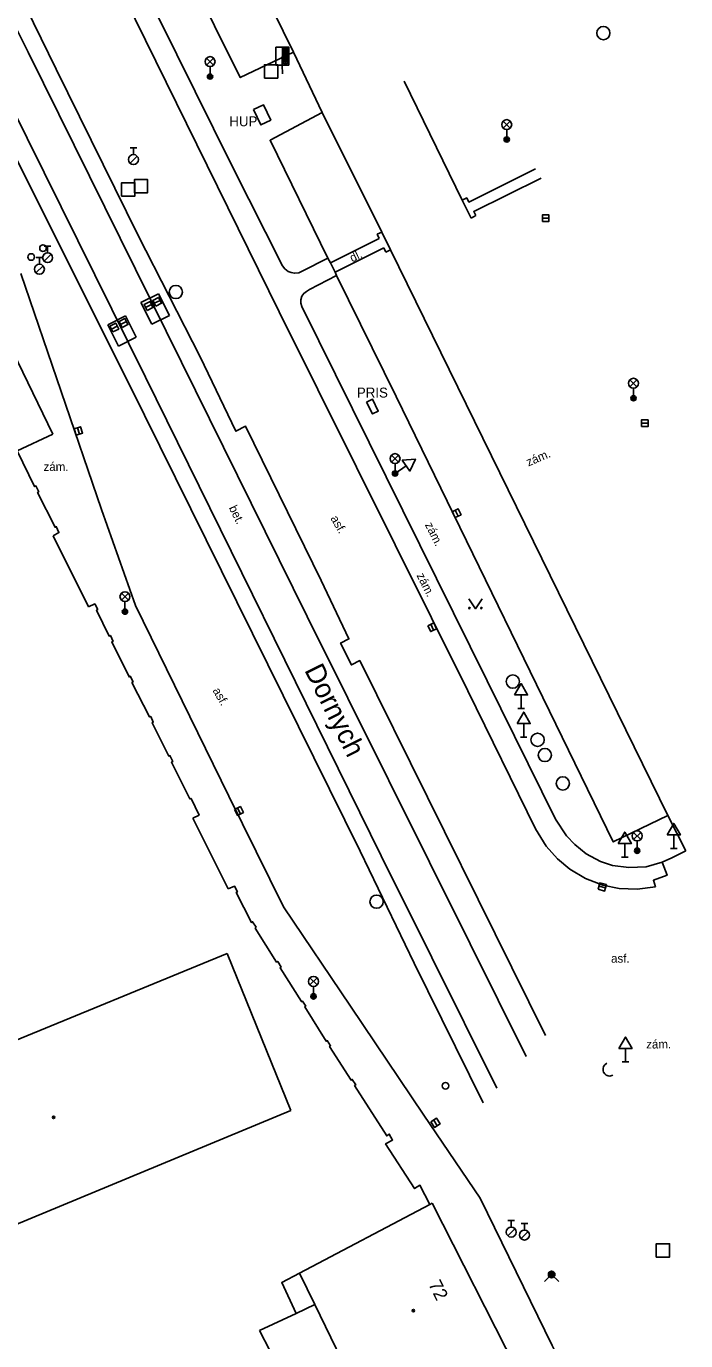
# Model space of a CAD drawing. Extents: x -598341 to -594502, y -1162301 to -1161406.
# Drawn here: x -597409.8 to -597360.1, y -1161848 to -1161748.9 of the extents above; entities that cross this region are included whole.
import ezdxf

# ---------------------------------------------------------------- set-up
doc = ezdxf.new("R2010")
doc.units = 0
for name, color, linetype in [('Vrstva 10', 7, 'Continuous'), ('Vrstva 11', 7, 'Continuous'), ('Vrstva 13', 7, 'Continuous'), ('Vrstva 24', 7, 'Continuous'), ('Vrstva 25', 7, 'Continuous'), ('Vrstva 26', 7, 'Continuous'), ('Vrstva 27', 7, 'Continuous'), ('Vrstva 28', 7, 'Continuous'), ('Vrstva 31', 7, 'Continuous'), ('Vrstva 33', 7, 'Continuous'), ('Vrstva 34', 7, 'Continuous'), ('Vrstva 36', 7, 'Continuous'), ('Vrstva 39', 7, 'Continuous'), ('Vrstva 40', 7, 'Continuous'), ('Vrstva 41', 7, 'Continuous'), ('Vrstva 46', 7, 'Continuous'), ('Vrstva 49', 7, 'Continuous'), ('Vrstva 5', 7, 'Continuous'), ('Vrstva 7', 7, 'Continuous'), ('Vrstva 8', 7, 'Continuous')]:
    doc.layers.add(name, color=color, linetype=linetype)

msp = doc.modelspace()

# ---------------------------------------------------------------- linework, layer by layer
at = {"layer": 'Vrstva 10'}
for p, q in [((-597386.89, -1161766.75), (-597387.07, -1161766.41)), ((-597386.53, -1161767.46), (-597386.89, -1161766.75)), ((-597386.42, -1161767.72), (-597386.53, -1161767.46))]:
    msp.add_line(p, q, dxfattribs=at)
for points in [[(-597389.67, -1161750.87), (-597393.69, -1161752.79), (-597397.56, -1161744.97), (-597401.57, -1161737.23), (-597397.36, -1161735.2)], [(-597371.42, -1161809.44), (-597376.52, -1161799.05), (-597381.99, -1161788.02), (-597390.76, -1161770.46), (-597405.49, -1161740.5), (-597407.78, -1161736.02)], [(-597387.5, -1161755.43), (-597389.67, -1161750.87)], [(-597387.07, -1161766.41), (-597391.44, -1161757.51), (-597387.5, -1161755.43)], [(-597410.23, -1161767.56), (-597404.14, -1161785.35), (-597401.58, -1161792.6), (-597394.55, -1161806.99), (-597390.42, -1161815.33), (-597385.37, -1161822.82), (-597379.83, -1161831.05), (-597375.6, -1161837.3), (-597370.15, -1161848.42), (-597368.22, -1161852.29)], [(-597361.45, -1161808.45), (-597365.56, -1161810.43), (-597381.92, -1161776.84), (-597386.42, -1161767.72)], [(-597360.09, -1161811.11), (-597361.45, -1161808.45)], [(-597371.42, -1161809.44), (-597370.61, -1161810.76), (-597369.75, -1161811.72), (-597368.83, -1161812.49), (-597367.64, -1161813.18), (-597366.34, -1161813.69), (-597365.11, -1161813.94), (-597363.76, -1161813.99), (-597362.36, -1161813.81)], [(-597365.59, -1161828.03), (-597365.81, -1161828.09), (-597365.94, -1161828.07), (-597366.08, -1161828.02), (-597366.2, -1161827.92), (-597366.28, -1161827.8), (-597366.32, -1161827.69), (-597366.32, -1161827.53), (-597366.29, -1161827.38), (-597366.19, -1161827.25), (-597366.04, -1161827.12)]]:
    msp.add_lwpolyline(points, dxfattribs=at)
at = {"layer": 'Vrstva 11'}
for p, q in [((-597381.32, -1161753.06), (-597376.96, -1161762.04)), ((-597383, -1161764.44), (-597387.5, -1161755.43)), ((-597383.2, -1161764.93), (-597386.89, -1161766.75)), ((-597383, -1161764.44), (-597383.36, -1161764.61)), ((-597383.36, -1161764.61), (-597383.2, -1161764.93)), ((-597383, -1161764.44), (-597382.35, -1161765.79)), ((-597386.53, -1161767.46), (-597382.85, -1161765.64)), ((-597382.85, -1161765.64), (-597382.7, -1161765.95)), ((-597382.7, -1161765.95), (-597382.35, -1161765.79)), ((-597361.45, -1161808.45), (-597382.35, -1161765.79)), ((-597387.07, -1161766.41), (-597389.01, -1161767.39)), ((-597388.45, -1161768.77), (-597386.42, -1161767.72)), ((-597401.17, -1161769.76), (-597399.84, -1161769.09)), ((-597400.36, -1161771.39), (-597401.17, -1161769.76)), ((-597399.84, -1161769.09), (-597399.03, -1161770.73)), ((-597403.67, -1161771.43), (-597402.34, -1161770.75)), ((-597402.34, -1161770.75), (-597401.53, -1161772.37)), ((-597399.03, -1161770.73), (-597400.36, -1161771.39)), ((-597402.87, -1161773.04), (-597403.67, -1161771.43)), ((-597401.53, -1161772.37), (-597402.87, -1161773.04))]:
    msp.add_line(p, q, dxfattribs=at)
for points in [[(-597375.36, -1161830.11), (-597380.56, -1161819.58), (-597384.65, -1161811.14), (-597402.07, -1161775.92), (-597412.64, -1161754.81), (-597417.86, -1161744.11), (-597420.13, -1161739.67), (-597423.19, -1161733.58), (-597428.01, -1161724.62)], [(-597370.66, -1161825.04), (-597374.47, -1161817.36), (-597384.67, -1161796.76), (-597385.3, -1161797.08), (-597386.12, -1161795.44), (-597385.49, -1161795.12), (-597387.58, -1161790.72), (-597393.28, -1161779.09), (-597394.01, -1161779.46), (-597396.71, -1161773.85), (-597401.38, -1161764.71), (-597407.57, -1161752.16), (-597411.57, -1161743.95), (-597417.12, -1161732.94), (-597417.69, -1161733.22)], [(-597390.5, -1161766.98), (-597394.33, -1161759.43), (-597404.02, -1161739.8), (-597407.38, -1161733.04), (-597398.74, -1161732.44)], [(-597389.67, -1161750.87), (-597397.36, -1161735.2)], [(-597371.42, -1161759.67), (-597376.44, -1161762.18), (-597376.6, -1161761.86), (-597376.96, -1161762.04)], [(-597375.92, -1161763.2), (-597376.08, -1161762.89), (-597370.98, -1161760.38)], [(-597376.96, -1161762.04), (-597376.28, -1161763.38)], [(-597376.28, -1161763.38), (-597375.92, -1161763.2)], [(-597390.5, -1161766.98), (-597390.32, -1161767.22), (-597390.08, -1161767.41), (-597389.84, -1161767.5), (-597389.6, -1161767.55), (-597389.27, -1161767.51), (-597389.01, -1161767.39)], [(-597389.05, -1161770.06), (-597389.11, -1161769.81), (-597389.12, -1161769.56), (-597389.03, -1161769.28), (-597388.89, -1161769.07), (-597388.7, -1161768.91), (-597388.45, -1161768.77)], [(-597369.9, -1161808.72), (-597375.07, -1161798.28), (-597389.05, -1161770.06)], [(-597361.87, -1161811.97), (-597363.08, -1161812.31), (-597364.37, -1161812.36), (-597365.61, -1161812.22), (-597366.51, -1161811.9), (-597367.59, -1161811.33), (-597368.46, -1161810.63), (-597369.09, -1161809.97), (-597369.9, -1161808.72)], [(-597361.14, -1161811.64), (-597360.09, -1161811.11)], [(-597361.87, -1161811.97), (-597361.49, -1161812.95), (-597362.52, -1161813.32), (-597362.36, -1161813.81)], [(-597361.87, -1161811.97), (-597361.14, -1161811.64)], [(-597389.47, -1161846), (-597390.55, -1161843.65), (-597389.21, -1161842.95)]]:
    msp.add_lwpolyline(points, dxfattribs=at)
at = {"layer": 'Vrstva 13'}
for points in [[(-597372.12, -1161826.62), (-597376.34, -1161818.13), (-597388.64, -1161793.42), (-597398.12, -1161774.25), (-597409.67, -1161750.87), (-597418.39, -1161733.44), (-597422.33, -1161726)], [(-597425.21, -1161726.89), (-597421.25, -1161734.37), (-597415.51, -1161745.76), (-597412.33, -1161752.23), (-597400.82, -1161775.37), (-597383.06, -1161811.47), (-597379.23, -1161819.14), (-597374.33, -1161829)]]:
    msp.add_lwpolyline(points, dxfattribs=at)
at = {"layer": 'Vrstva 24'}
msp.add_lwpolyline([(-597392.69, -1161755.2), (-597391.94, -1161754.84), (-597391.38, -1161756), (-597392.14, -1161756.36), (-597392.69, -1161755.2)], dxfattribs=at)
msp.add_lwpolyline([(-597384.166, -1161777.262), (-597383.723, -1161778.159), (-597383.275, -1161777.937), (-597383.718, -1161777.041)], close=True, dxfattribs=at)
at = {"layer": 'Vrstva 25'}
for p, q in [((-597391.012, -1161751.848), (-597391.012, -1161750.501)), ((-597391.012, -1161750.501), (-597390.511, -1161750.501)), ((-597390.511, -1161751.848), (-597391.012, -1161751.848)), ((-597390.51, -1161752.5), (-597390.511, -1161751.849))]:
    msp.add_line(p, q, dxfattribs=at)
for points in [[(-597390.01, -1161751.849), (-597390.511, -1161751.849), (-597390.51, -1161750.5), (-597390.011, -1161750.5)], [(-597390.11, -1161751.748), (-597390.41, -1161751.749), (-597390.409, -1161750.6), (-597390.111, -1161750.6)], [(-597390.21, -1161751.649), (-597390.31, -1161751.649), (-597390.31, -1161750.7), (-597390.21, -1161750.7)]]:
    msp.add_lwpolyline(points, close=True, dxfattribs=at)
at = {"layer": 'Vrstva 26'}
for points in [[(-597391.86, -1161752.82), (-597390.86, -1161752.82), (-597390.86, -1161751.82), (-597391.86, -1161751.82)], [(-597402.63, -1161761.72), (-597401.63, -1161761.72), (-597401.63, -1161760.72), (-597402.63, -1161760.72)], [(-597401.67, -1161761.48), (-597400.67, -1161761.48), (-597400.67, -1161760.48), (-597401.67, -1161760.48)], [(-597362.31, -1161841.74), (-597361.31, -1161841.74), (-597361.31, -1161840.74), (-597362.31, -1161840.74)]]:
    msp.add_lwpolyline(points, close=True, dxfattribs=at)
at = {"layer": 'Vrstva 27'}
for p, q in [((-597370.9, -1161763.39), (-597370.4, -1161763.39)), ((-597400.174, -1161769.812), (-597399.727, -1161769.588)), ((-597400.824, -1161770.132), (-597400.377, -1161769.908)), ((-597403.404, -1161771.752), (-597402.957, -1161771.528)), ((-597402.714, -1161771.412), (-597402.267, -1161771.188)), ((-597405.97, -1161779.203), (-597405.811, -1161779.677)), ((-597363.43, -1161778.86), (-597362.93, -1161778.86)), ((-597377.481, -1161785.416), (-597377.259, -1161785.864)), ((-597379.321, -1161794.016), (-597379.099, -1161794.464)), ((-597393.891, -1161807.876), (-597393.669, -1161808.324)), ((-597366.621, -1161813.764), (-597366.139, -1161813.896)), ((-597379.092, -1161831.407), (-597378.828, -1161831.832))]:
    msp.add_line(p, q, dxfattribs=at)
for points in [[(-597370.9, -1161763.64), (-597370.4, -1161763.64), (-597370.4, -1161763.14), (-597370.9, -1161763.14)], [(-597400.712, -1161770.355), (-597400.265, -1161770.132), (-597400.488, -1161769.685), (-597400.936, -1161769.908)], [(-597400.062, -1161770.035), (-597399.615, -1161769.812), (-597399.838, -1161769.365), (-597400.286, -1161769.588)], [(-597403.292, -1161771.975), (-597402.845, -1161771.752), (-597403.068, -1161771.305), (-597403.516, -1161771.528)], [(-597402.602, -1161771.635), (-597402.155, -1161771.412), (-597402.378, -1161770.965), (-597402.826, -1161771.188)], [(-597363.43, -1161779.11), (-597362.93, -1161779.11), (-597362.93, -1161778.61), (-597363.43, -1161778.61)], [(-597406.207, -1161779.283), (-597406.047, -1161779.757), (-597405.574, -1161779.597), (-597405.733, -1161779.124)], [(-597377.705, -1161785.527), (-597377.483, -1161785.975), (-597377.035, -1161785.753), (-597377.257, -1161785.305)], [(-597379.545, -1161794.127), (-597379.323, -1161794.575), (-597378.875, -1161794.353), (-597379.097, -1161793.905)], [(-597394.115, -1161807.987), (-597393.893, -1161808.435), (-597393.445, -1161808.213), (-597393.667, -1161807.765)], [(-597366.687, -1161814.005), (-597366.205, -1161814.137), (-597366.072, -1161813.655), (-597366.555, -1161813.523)], [(-597379.304, -1161831.539), (-597379.04, -1161831.964), (-597378.615, -1161831.7), (-597378.879, -1161831.275)]]:
    msp.add_lwpolyline(points, close=True, dxfattribs=at)
for centre in [(-597366.3, -1161749.43), (-597398.54, -1161768.96), (-597373.13, -1161798.34), (-597371.26, -1161802.73), (-597370.71, -1161803.88), (-597369.36, -1161806.02), (-597383.4, -1161814.94)]:
    msp.add_circle(centre, 0.5, dxfattribs=at)
at = {"layer": 'Vrstva 28'}
for p, q in [((-597401.998, -1161759.242), (-597401.468, -1161758.712)), ((-597401.99, -1161758.095), (-597401.49, -1161758.095)), ((-597401.74, -1161758.595), (-597401.74, -1161758.095)), ((-597408.46, -1161765.495), (-597407.96, -1161765.495)), ((-597408.21, -1161765.995), (-597408.21, -1161765.495)), ((-597409.08, -1161766.365), (-597408.58, -1161766.365)), ((-597408.83, -1161766.865), (-597408.83, -1161766.365)), ((-597408.468, -1161766.642), (-597407.938, -1161766.112)), ((-597409.088, -1161767.512), (-597408.558, -1161766.982)), ((-597373.5, -1161838.985), (-597373, -1161838.985)), ((-597373.25, -1161839.485), (-597373.25, -1161838.985)), ((-597372.5, -1161839.205), (-597372, -1161839.205)), ((-597372.25, -1161839.705), (-597372.25, -1161839.205)), ((-597373.508, -1161840.132), (-597372.978, -1161839.602)), ((-597372.508, -1161840.352), (-597371.978, -1161839.822))]:
    msp.add_line(p, q, dxfattribs=at)
for centre, radius in [((-597401.74, -1161758.97), 0.375), ((-597408.56, -1161765.65), 0.25), ((-597409.45, -1161766.32), 0.25), ((-597408.83, -1161767.24), 0.375), ((-597408.21, -1161766.37), 0.375), ((-597378.21, -1161828.82), 0.25), ((-597373.25, -1161839.86), 0.375), ((-597372.25, -1161840.08), 0.375)]:
    msp.add_circle(centre, radius, dxfattribs=at)
at = {"layer": 'Vrstva 31'}
msp.add_lwpolyline([(-597370.73, -1161843.58), (-597370.2, -1161843.05), (-597369.67, -1161843.58)], dxfattribs=at)
for radius in [0.25, 0.18, 0.11]:
    msp.add_circle((-597370.2, -1161843.05), radius, dxfattribs=at)
at = {"layer": 'Vrstva 33'}
for p, q in [((-597396.225, -1161751.85), (-597395.695, -1161751.32)), ((-597396.225, -1161751.32), (-597395.695, -1161751.85)), ((-597395.96, -1161751.96), (-597395.96, -1161752.71)), ((-597373.855, -1161756.6), (-597373.325, -1161756.07)), ((-597373.855, -1161756.07), (-597373.325, -1161756.6)), ((-597373.59, -1161756.71), (-597373.59, -1161757.46)), ((-597364.295, -1161776.11), (-597363.765, -1161775.58)), ((-597364.295, -1161775.58), (-597363.765, -1161776.11)), ((-597364.03, -1161776.22), (-597364.03, -1161776.97)), ((-597382.275, -1161781.79), (-597381.745, -1161781.26)), ((-597382.275, -1161781.26), (-597381.745, -1161781.79)), ((-597382.01, -1161781.9), (-597382.01, -1161782.65)), ((-597402.645, -1161792.2), (-597402.115, -1161791.67)), ((-597402.645, -1161791.67), (-597402.115, -1161792.2)), ((-597402.38, -1161792.31), (-597402.38, -1161793.06)), ((-597364.015, -1161810.24), (-597363.485, -1161809.71)), ((-597364.015, -1161809.71), (-597363.485, -1161810.24)), ((-597363.75, -1161810.35), (-597363.75, -1161811.1)), ((-597388.425, -1161821.22), (-597387.895, -1161820.69)), ((-597388.425, -1161820.69), (-597387.895, -1161821.22)), ((-597388.16, -1161821.33), (-597388.16, -1161822.08))]:
    msp.add_line(p, q, dxfattribs=at)
for centre, radius in [((-597395.96, -1161751.585), 0.375), ((-597395.96, -1161752.71), 0.2), ((-597395.96, -1161752.71), 0.145), ((-597395.96, -1161752.71), 0.0876), ((-597373.59, -1161756.335), 0.375), ((-597373.59, -1161757.46), 0.2), ((-597373.59, -1161757.46), 0.145), ((-597373.59, -1161757.46), 0.0876), ((-597364.03, -1161775.845), 0.375), ((-597364.03, -1161776.97), 0.2), ((-597364.03, -1161776.97), 0.145), ((-597364.03, -1161776.97), 0.0876), ((-597382.01, -1161781.525), 0.375), ((-597382.01, -1161782.65), 0.2), ((-597382.01, -1161782.65), 0.145), ((-597382.01, -1161782.65), 0.0876), ((-597402.38, -1161791.935), 0.375), ((-597402.38, -1161793.06), 0.2), ((-597402.38, -1161793.06), 0.145), ((-597402.38, -1161793.06), 0.0876), ((-597363.75, -1161809.975), 0.375), ((-597363.75, -1161811.1), 0.2), ((-597363.75, -1161811.1), 0.145), ((-597363.75, -1161811.1), 0.0876), ((-597388.16, -1161820.955), 0.375), ((-597388.16, -1161822.08), 0.2), ((-597388.16, -1161822.08), 0.145), ((-597388.16, -1161822.08), 0.0876)]:
    msp.add_circle(centre, radius, dxfattribs=at)
at = {"layer": 'Vrstva 34'}
for p, q in [((-597382.154, -1161782.446), (-597381.866, -1161782.854)), ((-597381.178, -1161782.063), (-597382.01, -1161782.65)), ((-597372.51, -1161799.352), (-597372.51, -1161800.37)), ((-597372.76, -1161800.37), (-597372.26, -1161800.37)), ((-597372.31, -1161801.512), (-597372.31, -1161802.53)), ((-597372.56, -1161802.53), (-597372.06, -1161802.53)), ((-597360.99, -1161809.902), (-597360.99, -1161810.92)), ((-597364.69, -1161810.552), (-597364.69, -1161811.57)), ((-597361.24, -1161810.92), (-597360.74, -1161810.92)), ((-597364.94, -1161811.57), (-597364.44, -1161811.57)), ((-597364.63, -1161826.012), (-597364.63, -1161827.03)), ((-597364.88, -1161827.03), (-597364.38, -1161827.03))]:
    msp.add_line(p, q, dxfattribs=at)
for points in [[(-597381.466, -1161781.654), (-597380.89, -1161782.471), (-597380.472, -1161781.563)], [(-597373.01, -1161799.352), (-597372.01, -1161799.352), (-597372.51, -1161798.486)], [(-597372.81, -1161801.512), (-597371.81, -1161801.512), (-597372.31, -1161800.646)], [(-597361.49, -1161809.902), (-597360.49, -1161809.902), (-597360.99, -1161809.036)], [(-597365.19, -1161810.552), (-597364.19, -1161810.552), (-597364.69, -1161809.686)], [(-597365.13, -1161826.012), (-597364.13, -1161826.012), (-597364.63, -1161825.146)]]:
    msp.add_lwpolyline(points, close=True, dxfattribs=at)
at = {"layer": 'Vrstva 36'}
msp.add_lwpolyline([(-597376.45, -1161792.1), (-597375.95, -1161792.85), (-597375.45, -1161792.1)], dxfattribs=at)
for centre in [(-597376.4, -1161792.8), (-597375.501, -1161792.8)]:
    msp.add_circle(centre, 0.05, dxfattribs=at)
at = {"layer": 'Vrstva 39'}
for centre, radius in [((-597407.76, -1161831.21), 0.09), ((-597407.76, -1161831.21), 0.0398), ((-597380.63, -1161845.78), 0.09), ((-597380.63, -1161845.78), 0.0398)]:
    msp.add_circle(centre, radius, dxfattribs=at)
at = {"layer": 'Vrstva 5'}
for p, q in [((-597411.2, -1161772.67), (-597407.83, -1161779.67)), ((-597407.83, -1161779.67), (-597410.5, -1161780.95)), ((-597413.86, -1161826.74), (-597394.67, -1161818.85)), ((-597394.67, -1161818.85), (-597389.86, -1161830.69)), ((-597389.86, -1161830.69), (-597423.14, -1161844.49)), ((-597389.21, -1161842.95), (-597379.39, -1161837.77)), ((-597379.39, -1161837.77), (-597379.22, -1161837.68)), ((-597379.22, -1161837.68), (-597372.84, -1161850.2)), ((-597388.06, -1161845.31), (-597389.21, -1161842.95)), ((-597392.24, -1161847.28), (-597389.47, -1161846)), ((-597388.06, -1161845.31), (-597389.47, -1161846)), ((-597384.67, -1161852.29), (-597388.06, -1161845.31)), ((-597389.7, -1161852.15), (-597392.24, -1161847.28))]:
    msp.add_line(p, q, dxfattribs=at)
at = {"layer": 'Vrstva 7'}
for points in [[(-597410.5, -1161780.95), (-597409.19, -1161783.64), (-597409.1, -1161783.59), (-597408.88, -1161784.02), (-597408.97, -1161784.07), (-597407.65, -1161786.7), (-597407.56, -1161786.65), (-597407.36, -1161787.1), (-597407.79, -1161787.34)], [(-597405.13, -1161792.71), (-597404.66, -1161792.48), (-597404.43, -1161792.9), (-597404.52, -1161792.95), (-597403.57, -1161794.91), (-597403.48, -1161794.87), (-597403.28, -1161795.31), (-597403.37, -1161795.35), (-597402.07, -1161797.99), (-597401.98, -1161797.94), (-597401.76, -1161798.37), (-597401.85, -1161798.42), (-597400.53, -1161801.01), (-597400.44, -1161800.97), (-597400.24, -1161801.4), (-597400.33, -1161801.44), (-597399.08, -1161803.96), (-597398.99, -1161803.92), (-597398.78, -1161804.38), (-597398.87, -1161804.42), (-597397.48, -1161807.19), (-597397.39, -1161807.15), (-597396.79, -1161808.41), (-597397.25, -1161808.63)], [(-597394.59, -1161813.97), (-597394.13, -1161813.76), (-597393.9, -1161814.2), (-597393.99, -1161814.24), (-597392.84, -1161816.5), (-597392.75, -1161816.45), (-597392.49, -1161816.87), (-597392.57, -1161816.93), (-597390.94, -1161819.5), (-597390.86, -1161819.45), (-597390.6, -1161819.87), (-597390.68, -1161819.92), (-597389.07, -1161822.48), (-597388.99, -1161822.43), (-597388.74, -1161822.81), (-597388.82, -1161822.86), (-597387.2, -1161825.46), (-597387.12, -1161825.41), (-597386.87, -1161825.8), (-597386.95, -1161825.85), (-597385.32, -1161828.39), (-597385.24, -1161828.34), (-597384.98, -1161828.76), (-597385.06, -1161828.81), (-597382.63, -1161832.6), (-597382.45, -1161832.47), (-597382.2, -1161832.92), (-597382.72, -1161833.21), (-597380.54, -1161836.58), (-597380.13, -1161836.32), (-597379.39, -1161837.77)]]:
    msp.add_lwpolyline(points, dxfattribs=at)
at = {"layer": 'Vrstva 8'}
for p, q in [((-597405.13, -1161792.71), (-597407.79, -1161787.34)), ((-597394.59, -1161813.97), (-597397.25, -1161808.63))]:
    msp.add_line(p, q, dxfattribs=at)

# ---------------------------------------------------------------- texts
at = {"layer": 'Vrstva 40'}
for s, height, rotation, p in [(' dl.', 0.6499, 26.3154, (-597385.45, -1161766.84)), ('zám.', 0.65, 22.97004, (-597371.95, -1161782.12)), ('bet.', 0.65, 296.29791, (-597394.56, -1161785.24)), ('asf.', 0.65, 299.67996, (-597386.9, -1161786.03)), ('zám.', 0.65, 296.34782, (-597379.77, -1161786.51)), ('zám.', 0.65, 296.34782, (-597380.4, -1161790.33)), ('asf.', 0.65, 299.67996, (-597395.79, -1161799.01))]:
    msp.add_text(s, height=height, rotation=rotation, dxfattribs=at).set_placement(p)
for s, p in [('zám.', (-597408.52, -1161782.46)), ('asf.', (-597365.72, -1161819.54)), ('zám.', (-597363.07, -1161826.01))]:
    msp.add_text(s, height=0.65, dxfattribs=at).set_placement(p)
at = {"layer": 'Vrstva 41'}
for s, p in [('HUP', (-597394.51, -1161756.46)), ('PRIS', (-597384.89, -1161776.92))]:
    msp.add_text(s, height=0.75, dxfattribs=at).set_placement(p)
at = {"layer": 'Vrstva 46'}
msp.add_text('72', height=1, rotation=296.39, dxfattribs=at).set_placement((-597379.52, -1161843.78))
at = {"layer": 'Vrstva 49'}
msp.add_text('Dornych', height=1.5, rotation=296.39, dxfattribs=at).set_placement((-597388.87, -1161797.47))

doc.saveas('drawing.dxf')
